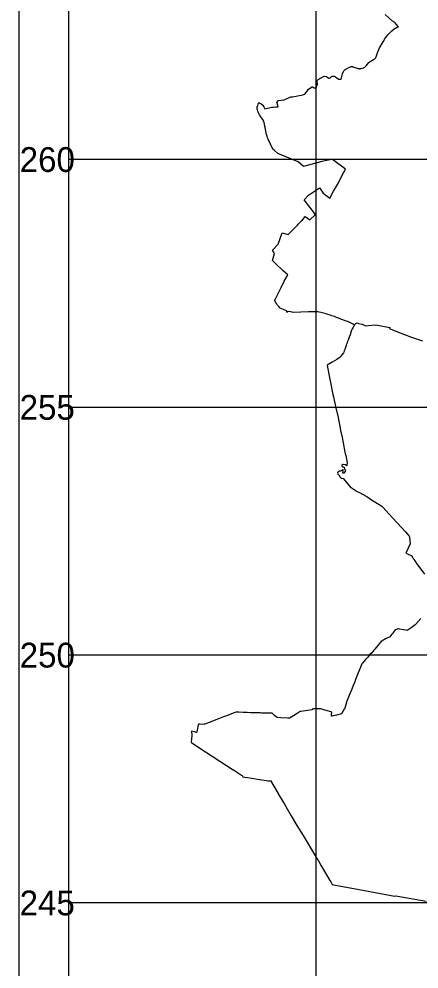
# Model space of a CAD drawing. Extents: x 459000 to 506121, y 225400 to 317424.
# Drawn here: x 459000 to 467082, y 243667 to 262836 of the extents above; entities that cross this region are included whole.
import ezdxf

# ---------------------------------------------------------------- set-up
doc = ezdxf.new("R2010")
doc.units = 0
for name, color, linetype in [('novada_robeza', 7, 'Continuous'), ('pagastu_robezas', 7, 'Continuous'), ('Ramis', 7, 'Continuous'), ('valsts_robeza', 7, 'Continuous')]:
    doc.layers.add(name, color=color, linetype=linetype)

msp = doc.modelspace()

# ---------------------------------------------------------------- linework, layer by layer
at = {"layer": 'novada_robeza'}
for points in [[(463847, 261148), (463849, 261147), (463851, 261146), (463890, 261123), (463928, 261099), (463948, 261063), (463968, 261026), (464109, 261056), (464136, 261058), (464141, 261058), (464188, 261061), (464236, 261063), (464214, 261141), (464211, 261150), (464240, 261191), (464294, 261198), (464352, 261205), (464360, 261206), (464494, 261266), (464522, 261266), (464603, 261280), (464660, 261291), (464707, 261301), (464735, 261308), (464780, 261328), (464798, 261344), (464821, 261378), (464848, 261419), (464920, 261469), (464928, 261468), (464964, 261448), (464980, 261445), (464994, 261447), (465004, 261456), (465010, 261463), (465019, 261490), (465028, 261524), (465023, 261574), (465029, 261599), (465041, 261614), (465152, 261673), (465167, 261683), (465211, 261675), (465244, 261648), (465255, 261643), (465272, 261640), (465287, 261646), (465310, 261670), (465331, 261682), (465348, 261685), (465367, 261682), (465394, 261671), (465431, 261645), (465459, 261623), (465481, 261620), (465502, 261623), (465508, 261623), (465538, 261727), (465549, 261765), (465562, 261787), (465572, 261799), (465587, 261815), (465606, 261826), (465678, 261866), (465695, 261873), (465710, 261875), (465714, 261876), (465717, 261877), (465724, 261876), (465731, 261876), (465736, 261875), (465742, 261874), (465752, 261870), (465762, 261867), (465787, 261859), (465812, 261851), (465829, 261845), (465846, 261840), (465855, 261837), (465865, 261835), (465871, 261834), (465878, 261833), (465884, 261833), (465890, 261833), (465900, 261836), (465910, 261840), (465934, 261846), (465958, 261852), (465972, 261859), (465985, 261867), (465998, 261880), (466012, 261892), (466041, 261925), (466071, 261959), (466082, 261967), (466094, 261976), (466128, 261998), (466162, 262019), (466170, 262021), (466178, 262024), (466186, 262030), (466202, 262043), (466218, 262074), (466238, 262133), (466246, 262156), (466280, 262255), (466355, 262374), (466375, 262400), (466387, 262426), (466425, 262485), (466457, 262522), (466492, 262554), (466496, 262561), (466533, 262595), (466582, 262637), (466606, 262654), (466641, 262674), (466649, 262676), (466668, 262676), (466662, 262682), (466595, 262764), (466546, 262791), (466401, 262928)], [(464119, 257963), (464165, 258102), (464123, 258170), (464234, 258296), (464319, 258521), (464436, 258489), (464571, 258619), (464625, 258678), (464640, 258694), (464698, 258758), (464717, 258763), (464782, 258852), (464876, 258784), (464988, 258894), (464764, 259190), (464848, 259282), (465069, 259427), (465146, 259325), (465278, 259222), (465352, 259359), (465432, 259500), (465553, 259730), (465595, 259808), (465335, 260001), (465317, 260000), (465115, 259963), (464751, 259859), (464637, 259952), (464230, 260122), (464155, 260192), (464130, 260213), (464032, 260409), (464021, 260437), (464012, 260463), (464001, 260505), (463972, 260650), (463967, 260670), (463960, 260711), (463946, 260772), (463936, 260795), (463933, 260801), (463929, 260806), (463929, 260806), (463929, 260805), (463900, 260845), (463871, 260884), (463861, 260901), (463851, 260917), (463844, 260931), (463837, 260945), (463830, 260961), (463824, 260978), (463817, 261001), (463811, 261025), (463811, 261033), (463812, 261042), (463813, 261057), (463815, 261071), (463819, 261080), (463822, 261089), (463835, 261118), (463847, 261148)], [(465775, 256666), (465726, 256690), (465655, 256723), (465619, 256737), (465587, 256746), (465541, 256763), (465501, 256778), (465454, 256797), (465417, 256814), (465374, 256831), (465321, 256850), (465288, 256860), (465237, 256876), (465206, 256886), (465122, 256907), (465037, 256928), (464942, 256928), (464846, 256928), (464694, 256922), (464541, 256917), (464491, 256927), (464440, 256937), (464433, 256934), (464426, 256930), (464421, 256923), (464415, 256916), (464411, 256932), (464407, 256948), (464341, 256976), (464275, 257004), (464247, 257037), (464219, 257070), (464191, 257115), (464163, 257161), (464174, 257179), (464194, 257218), (464297, 257418), (464360, 257544), (464428, 257675), (464338, 257757), (464184, 257904), (464125, 257958), (464119, 257963)], [(465775, 256666), (465744, 256605), (465731, 256583), (465713, 256535), (465688, 256466), (465669, 256414), (465650, 256359), (465633, 256312), (465622, 256282), (465611, 256253), (465595, 256207), (465580, 256168), (465571, 256142), (465561, 256116), (465555, 256097), (465531, 256069), (465484, 256012), (465471, 255998), (465421, 255968), (465324, 255911), (465226, 255853), (465227, 255845), (465338, 255261), (465354, 255213), (465397, 255020), (465445, 254793), (465459, 254721), (465479, 254623), (465497, 254535), (465527, 254389), (465564, 254208), (465571, 254172), (465586, 254099), (465599, 254038), (465601, 254033), (465602, 254029), (465625, 253919), (465626, 253912), (465630, 253878), (465625, 253829), (465620, 253822), (465594, 253840), (465549, 253849), (465534, 253844), (465529, 253841), (465524, 253832), (465522, 253821), (465528, 253807), (465536, 253802), (465557, 253799), (465563, 253796), (465568, 253791), (465572, 253780), (465576, 253770), (465578, 253758), (465583, 253747), (465591, 253741), (465594, 253738), (465595, 253732), (465592, 253720), (465587, 253707), (465564, 253675), (465560, 253672), (465553, 253671), (465544, 253672), (465544, 253684), (465551, 253722), (465552, 253733), (465551, 253736), (465545, 253739), (465536, 253740), (465533, 253738), (465528, 253733), (465521, 253724), (465512, 253719), (465502, 253717), (465490, 253714), (465471, 253711), (465462, 253708), (465450, 253700), (465443, 253691), (465435, 253672), (465439, 253652), (465446, 253644), (465458, 253638), (465467, 253629), (465476, 253617), (465485, 253598), (465504, 253578), (465520, 253563), (465531, 253569), (465552, 253563), (465690, 253398), (465834, 253305), (465864, 253286), (466024, 253200), (466096, 253154), (466104, 253149), (466333, 253009), (466352, 252988), (466357, 252978), (466473, 252852), (466800, 252496), (466807, 252486), (466881, 252400), (466888, 252385), (466906, 252247), (466819, 252069), (466815, 252062), (466860, 252039), (466924, 252008), (466939, 252001), (466943, 251999), (466944, 251990), (466944, 251981), (466945, 251979), (466946, 251977), (466953, 251967), (466960, 251956), (466978, 251930), (466996, 251904), (467011, 251883), (467025, 251861), (467033, 251852), (467058, 251819), (467194, 251633)], [(467117, 250738), (467061, 250676), (467004, 250613), (466924, 250554), (466844, 250495), (466816, 250501), (466760, 250510), (466689, 250527), (466670, 250530), (466660, 250530), (466653, 250528), (466639, 250525), (466622, 250519), (466613, 250514), (466603, 250509), (466581, 250486), (466550, 250445), (466532, 250421), (466491, 250372), (466476, 250361), (466404, 250326), (466318, 250273), (466288, 250239), (466279, 250230), (466189, 250122), (466171, 250102), (466125, 250050), (466091, 250010), (466049, 249962), (466003, 249909), (465962, 249862), (465940, 249835), (465939, 249834), (465936, 249833), (465928, 249826), (465801, 249511), (465782, 249464), (465752, 249390), (465723, 249316), (465666, 249175), (465609, 249035), (465615, 249032), (465610, 249020), (465596, 248978), (465573, 248913), (465571, 248907), (465514, 248815), (465414, 248786), (465324, 248770), (465313, 248768), (465315, 248808), (465317, 248840), (465316, 248848), (465314, 248853), (465312, 248854), (465277, 248864), (465230, 248878), (465161, 248899), (465119, 248912), (465101, 248917), (465093, 248920), (465012, 248920), (464993, 248920), (464959, 248914), (464934, 248909), (464923, 248907), (464924, 248894), (464692, 248864), (464682, 248863), (464637, 248833), (464597, 248809), (464543, 248776), (464466, 248729), (464429, 248730), (464293, 248736), (464218, 248740), (464172, 248776), (464112, 248826), (463993, 248829), (463902, 248832), (463872, 248834), (463828, 248836), (463808, 248836), (463762, 248836), (463679, 248839), (463610, 248842), (463529, 248845), (463442, 248849), (463410, 248849), (463380, 248848), (463350, 248836), (463190, 248773), (463130, 248753), (463029, 248713), (462842, 248643), (462752, 248608), (462741, 248605), (462715, 248601), (462654, 248609), (462647, 248610), (462641, 248608), (462623, 248597), (462622, 248592), (462601, 248485), (462592, 248446), (462586, 248440), (462581, 248440), (462545, 248450), (462487, 248468), (462485, 248464), (462490, 248378), (462480, 248245), (462479, 248238)]]:
    msp.add_lwpolyline(points, dxfattribs=at)
at = {"layer": 'pagastu_robezas'}
msp.add_lwpolyline([(465775, 256666), (465803, 256693), (465830, 256703), (465862, 256695), (465935, 256678), (465998, 256646), (466190, 256664), (466240, 256656), (466491, 256614), (466489, 256602), (466483, 256595), (466486, 256593), (466548, 256564), (466789, 256468), (466927, 256418), (467032, 256380), (467155, 256341)], dxfattribs=at)
at = {"layer": 'Ramis'}
for p, q in [((459000, 311000), (459000, 225400)), ((460000, 310000), (460000, 240000)), ((465000, 310000), (465000, 240000)), ((505000, 260000), (460000, 260000)), ((505000, 255000), (460000, 255000)), ((505000, 250000), (460000, 250000)), ((505000, 245000), (460000, 245000))]:
    msp.add_line(p, q, dxfattribs=at)
at = {"layer": 'valsts_robeza'}
msp.add_lwpolyline([(462479, 248238), (462483, 248235), (462634, 248137), (463328, 247684), (463335, 247683), (463498, 247581), (463510, 247570), (463517, 247558), (463522, 247547), (463562, 247539), (463618, 247530), (463707, 247515), (463856, 247492), (463954, 247478), (463995, 247471), (464027, 247466), (464042, 247464), (464060, 247464), (464080, 247468), (464235, 247210), (464239, 247201), (464330, 247047), (464364, 246994), (464502, 246755), (464616, 246564), (464740, 246361), (464799, 246258), (464927, 246045), (465007, 245918), (465024, 245892), (465046, 245856), (465048, 245852), (465107, 245750), (465282, 245456), (465302, 245423), (465326, 245375), (465353, 245365), (465766, 245290), (466520, 245149), (466554, 245143), (466595, 245140), (466616, 245145), (467224, 245034)], dxfattribs=at)

# ---------------------------------------------------------------- texts
at = {"layer": 'Ramis'}
for s, p in [('260', (459014, 259750)), ('255', (459013, 254750)), ('250', (459014, 249750)), ('245', (459013, 244750))]:
    msp.add_text(s, height=500, dxfattribs=at).set_placement(p)

doc.saveas('drawing.dxf')
